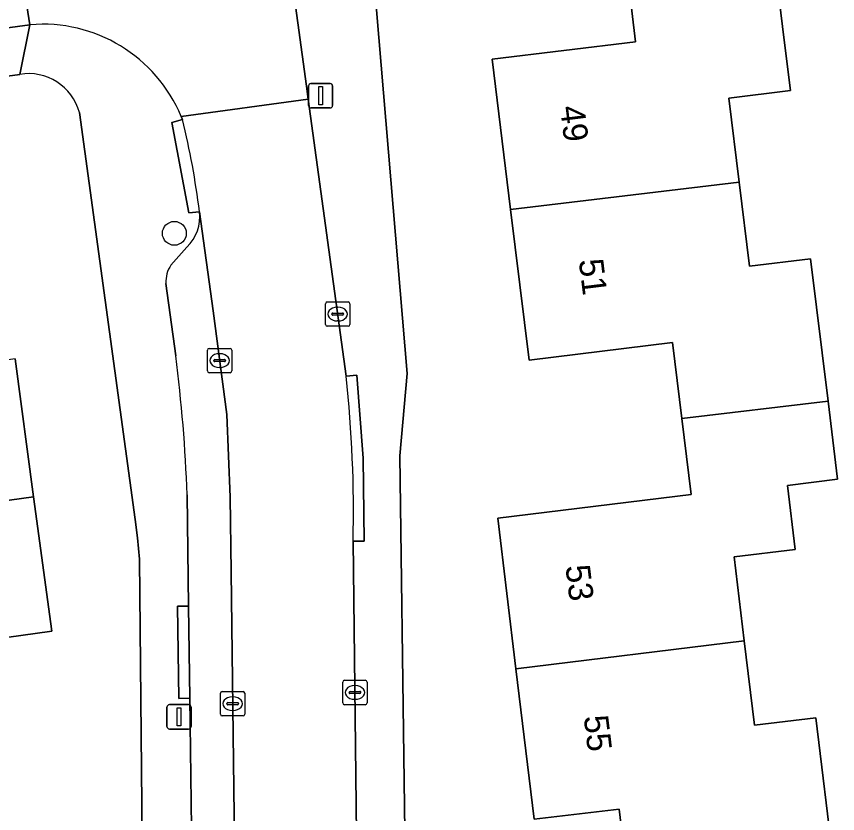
# Model space of a CAD drawing. Extents: x 163426 to 164192, y 380329 to 381641.
# Drawn here: x 163603.52 to 163637.18, y 380953.62 to 380986.28 of the extents above; entities that cross this region are included whole.
import ezdxf

# ---------------------------------------------------------------- set-up
doc = ezdxf.new("R2010")
doc.units = 0
for name, color, linetype in [('IMGEO_Boom', 7, 'Continuous'), ('IMGEO_Erf', 7, 'Continuous'), ('IMGEO_Kolk', 7, 'Continuous'), ('IMGEO_Lichtmast', 7, 'Continuous'), ('IMGEO_Pand', 7, 'Continuous'), ('IMGEO_Pand_nummerreeks', 7, 'Continuous'), ('IMGEO_Parkeervlak_open', 7, 'Continuous'), ('IMGEO_Rijbaan_lokaal_open', 7, 'Continuous'), ('IMGEO_Voetpad_open', 7, 'Continuous')]:
    doc.layers.add(name, color=color, linetype=linetype)

msp = doc.modelspace()

# ---------------------------------------------------------------- linework, layer by layer
at = {"layer": 'IMGEO_Boom'}
msp.add_circle((163609.992, 380977.393), 0.489, dxfattribs=at)
at = {"layer": 'IMGEO_Erf'}
for points in [[(163617.891, 380991.091), (163619.538, 380971.648), (163619.238, 380968.276), (163619.763, 380928.298)], [(163628.589, 380950.731), (163628.222, 380953.805), (163624.741, 380953.39), (163623.993, 380959.552), (163623.245, 380965.718), (163631.178, 380966.696), (163630.794, 380969.807), (163630.41, 380972.923), (163624.53, 380972.198), (163623.775, 380978.366), (163623.021, 380984.53), (163628.892, 380985.235), (163628.289, 380990.329)], [(163634.371, 380990.377), (163634.977, 380985.414), (163635.242, 380983.242), (163632.722, 380982.935), (163633.142, 380979.492), (163633.563, 380976.048), (163636.073, 380976.355), (163636.785, 380970.521), (163637.177, 380967.315), (163635.123, 380967.064), (163635.443, 380964.444), (163632.932, 380964.138), (163633.352, 380960.694), (163633.774, 380957.241), (163636.285, 380957.548), (163637.012, 380951.59)], [(163603.654, 380983.906), (163596.929, 380982.994)], [(163608.56, 380964.048), (163608.482, 380964.92), (163608.391, 380965.666), (163606.099, 380982.34)], [(163603.462, 380972.248), (163604.225, 380966.6), (163604.97, 380961.09), (163599.97, 380960.4)], [(163609.036, 380928.48), (163608.809, 380938.199), (163608.56, 380964.048)]]:
    msp.add_lwpolyline(points, dxfattribs=at)
msp.add_arc((163604.011, 380981.772), 2.164, 15.2262, 99.4954, dxfattribs=at)
at = {"layer": 'IMGEO_Kolk'}
for p, q in [((163616.261, 380974.584), (163617.113, 380974.584)), ((163616.186, 380973.658), (163616.186, 380974.51)), ((163616.674, 380974.364), (163616.699, 380974.364)), ((163617.187, 380974.51), (163617.187, 380973.658)), ((163616.445, 380974.078), (163616.445, 380974.09)), ((163616.883, 380974.041), (163616.485, 380974.041)), ((163616.488, 380974.127), (163616.886, 380974.127)), ((163616.929, 380974.09), (163616.929, 380974.078)), ((163617.113, 380973.584), (163616.261, 380973.584)), ((163616.697, 380973.804), (163616.672, 380973.804)), ((163611.347, 380971.754), (163611.347, 380972.606)), ((163611.422, 380972.68), (163612.274, 380972.68)), ((163612.348, 380972.606), (163612.348, 380971.754)), ((163611.649, 380972.223), (163612.047, 380972.223)), ((163611.835, 380972.46), (163611.86, 380972.46)), ((163611.606, 380972.174), (163611.606, 380972.186)), ((163612.044, 380972.137), (163611.646, 380972.137)), ((163611.858, 380971.9), (163611.833, 380971.9)), ((163612.09, 380972.186), (163612.09, 380972.174)), ((163612.274, 380971.68), (163611.422, 380971.68)), ((163616.892, 380958.156), (163616.892, 380959.008)), ((163616.967, 380959.082), (163617.819, 380959.082)), ((163617.38, 380958.862), (163617.405, 380958.862)), ((163617.893, 380959.008), (163617.893, 380958.156)), ((163611.881, 380957.697), (163611.881, 380958.549)), ((163611.956, 380958.623), (163612.808, 380958.623)), ((163612.882, 380958.549), (163612.882, 380957.697)), ((163617.151, 380958.576), (163617.151, 380958.588)), ((163617.589, 380958.539), (163617.191, 380958.539)), ((163617.194, 380958.625), (163617.592, 380958.625)), ((163617.635, 380958.588), (163617.635, 380958.576)), ((163612.14, 380958.117), (163612.14, 380958.129)), ((163612.578, 380958.08), (163612.18, 380958.08)), ((163612.183, 380958.166), (163612.581, 380958.166)), ((163612.369, 380958.403), (163612.394, 380958.403)), ((163612.624, 380958.129), (163612.624, 380958.117)), ((163617.819, 380958.082), (163616.967, 380958.082)), ((163617.403, 380958.302), (163617.378, 380958.302)), ((163612.392, 380957.843), (163612.367, 380957.843)), ((163612.808, 380957.623), (163611.956, 380957.623))]:
    msp.add_line(p, q, dxfattribs=at)
for points in [[(163616.261, 380974.584), (163617.113, 380974.584)], [(163616.186, 380973.658), (163616.186, 380974.51)], [(163617.187, 380974.51), (163617.187, 380973.658)], [(163617.113, 380973.584), (163616.261, 380973.584)], [(163611.347, 380971.754), (163611.347, 380972.606)], [(163611.422, 380972.68), (163612.274, 380972.68)], [(163612.348, 380972.606), (163612.348, 380971.754)], [(163612.274, 380971.68), (163611.422, 380971.68)], [(163616.892, 380958.156), (163616.892, 380959.008)], [(163616.967, 380959.082), (163617.819, 380959.082)], [(163617.893, 380959.008), (163617.893, 380958.156)], [(163611.881, 380957.697), (163611.881, 380958.549)], [(163611.956, 380958.623), (163612.808, 380958.623)], [(163612.882, 380958.549), (163612.882, 380957.697)], [(163617.819, 380958.082), (163616.967, 380958.082)], [(163612.808, 380957.623), (163611.956, 380957.623)]]:
    msp.add_lwpolyline(points, dxfattribs=at)
for centre, radius, start, end in [((163616.263, 380974.508), 0.0765, 91.552, 178.448), ((163616.263, 380974.508), 0.0765, 91.552, 178.448), ((163617.111, 380974.508), 0.0765, 1.552, 88.448), ((163617.111, 380974.508), 0.0765, 1.552, 88.448), ((163616.485, 380974.087), 0.0403, 85.8775, 175.7526), ((163616.482, 380974.077), 0.0366, 178.938, 274.7102), ((163616.886, 380974.084), 0.043, 264.8664, 352.4533), ((163616.89, 380974.089), 0.0386, 1.7309, 96.639), ((163616.263, 380973.66), 0.0765, 181.552, 268.448), ((163616.263, 380973.66), 0.0765, 181.552, 268.448), ((163617.111, 380973.66), 0.0765, 271.552, 358.448), ((163617.111, 380973.66), 0.0765, 271.552, 358.448), ((163611.424, 380972.604), 0.0765, 91.552, 178.448), ((163611.424, 380972.604), 0.0765, 91.552, 178.448), ((163612.272, 380972.604), 0.0765, 1.552, 88.448), ((163612.272, 380972.604), 0.0765, 1.552, 88.448), ((163611.646, 380972.183), 0.0403, 85.8775, 175.7526), ((163612.051, 380972.185), 0.0386, 1.7309, 96.639), ((163611.643, 380972.173), 0.0366, 178.938, 274.7102), ((163612.047, 380972.18), 0.043, 264.8664, 352.4533), ((163611.424, 380971.756), 0.0765, 181.552, 268.448), ((163611.424, 380971.756), 0.0765, 181.552, 268.448), ((163612.272, 380971.756), 0.0765, 271.552, 358.448), ((163612.272, 380971.756), 0.0765, 271.552, 358.448), ((163616.969, 380959.006), 0.0765, 91.552, 178.448), ((163616.969, 380959.006), 0.0765, 91.552, 178.448), ((163617.817, 380959.006), 0.0765, 1.552, 88.448), ((163617.817, 380959.006), 0.0765, 1.552, 88.448), ((163611.958, 380958.547), 0.0765, 91.552, 178.448), ((163611.958, 380958.547), 0.0765, 91.552, 178.448), ((163612.806, 380958.547), 0.0765, 1.552, 88.448), ((163612.806, 380958.547), 0.0765, 1.552, 88.448), ((163617.191, 380958.585), 0.0403, 85.8775, 175.7526), ((163617.188, 380958.575), 0.0366, 178.938, 274.7102), ((163617.592, 380958.582), 0.043, 264.8664, 352.4533), ((163617.596, 380958.587), 0.0386, 1.7309, 96.639), ((163612.18, 380958.126), 0.0403, 85.8775, 175.7526), ((163612.177, 380958.116), 0.0366, 178.938, 274.7102), ((163612.581, 380958.123), 0.043, 264.8664, 352.4533), ((163612.585, 380958.128), 0.0386, 1.7309, 96.639), ((163616.969, 380958.158), 0.0765, 181.552, 268.448), ((163616.969, 380958.158), 0.0765, 181.552, 268.448), ((163617.817, 380958.158), 0.0765, 271.552, 358.448), ((163617.817, 380958.158), 0.0765, 271.552, 358.448), ((163611.958, 380957.699), 0.0765, 181.552, 268.448), ((163611.958, 380957.699), 0.0765, 181.552, 268.448), ((163612.806, 380957.699), 0.0765, 271.552, 358.448), ((163612.806, 380957.699), 0.0765, 271.552, 358.448)]:
    msp.add_arc(centre, radius, start, end, dxfattribs=at)
for centre, major_axis, ratio, start_param, end_param in [((163616.673, 380974.084), (-0.387, 0.002), 0.722429, 4.712389, 7.853982), ((163616.698, 380974.084), (-0.39, 0.002), 0.717154, 1.570796, 4.712389), ((163611.834, 380972.18), (-0.387, 0.002), 0.722429, 4.712389, 7.853982), ((163611.859, 380972.18), (-0.39, 0.002), 0.717154, 1.570796, 4.712389), ((163617.379, 380958.582), (-0.387, 0.002), 0.722429, 4.712389, 7.853982), ((163617.404, 380958.582), (-0.39, 0.002), 0.717154, 1.570796, 4.712389), ((163612.368, 380958.123), (-0.387, 0.002), 0.722429, 4.712389, 7.853982), ((163612.393, 380958.123), (-0.39, 0.002), 0.717154, 1.570796, 4.712389)]:
    msp.add_ellipse(centre, major_axis=major_axis, ratio=ratio, start_param=start_param, end_param=end_param, dxfattribs=at)
at = {"layer": 'IMGEO_Lichtmast'}
for p, q in [((163615.49, 380982.629), (163615.49, 380983.429)), ((163615.49, 380983.429), (163615.49, 380982.629)), ((163615.59, 380983.529), (163616.38, 380983.529)), ((163616.38, 380983.529), (163615.59, 380983.529)), ((163616.48, 380983.429), (163616.48, 380982.629)), ((163616.48, 380982.629), (163616.48, 380983.429)), ((163616.38, 380982.529), (163615.59, 380982.529)), ((163615.59, 380982.529), (163616.38, 380982.529)), ((163609.789, 380958.085), (163610.579, 380958.085)), ((163610.579, 380958.085), (163609.789, 380958.085)), ((163609.689, 380957.185), (163609.689, 380957.985)), ((163609.689, 380957.985), (163609.689, 380957.185)), ((163610.679, 380957.985), (163610.679, 380957.185)), ((163610.679, 380957.185), (163610.679, 380957.985)), ((163610.579, 380957.085), (163609.789, 380957.085)), ((163609.789, 380957.085), (163610.579, 380957.085))]:
    msp.add_line(p, q, dxfattribs=at)
for points in [[(163615.91, 380983.404), (163616.06, 380983.404), (163616.06, 380982.654), (163615.91, 380982.654), (163615.91, 380983.404)], [(163610.109, 380957.96), (163610.259, 380957.96), (163610.259, 380957.21), (163610.109, 380957.21), (163610.109, 380957.96)]]:
    msp.add_lwpolyline(points, dxfattribs=at)
for centre, start, end in [((163615.59, 380983.429), 90, 180), ((163615.59, 380983.429), 90, 180), ((163616.38, 380983.429), 0, 90), ((163616.38, 380983.429), 360, 90), ((163615.59, 380982.629), 180, 270), ((163615.59, 380982.629), 180, 270), ((163616.38, 380982.629), 270, 0), ((163616.38, 380982.629), 270, 0), ((163609.789, 380957.985), 90, 180), ((163609.789, 380957.985), 90, 180), ((163610.579, 380957.985), 0, 90), ((163610.579, 380957.985), 360, 90), ((163609.789, 380957.185), 180, 270), ((163609.789, 380957.185), 180, 270), ((163610.579, 380957.185), 270, 0), ((163610.579, 380957.185), 270, 0)]:
    msp.add_arc(centre, 0.1, start, end, dxfattribs=at)
at = {"layer": 'IMGEO_Pand'}
for points in [[(163634.977, 380985.414), (163634.371, 380990.377), (163633.385, 380990.42), (163627.777, 380990.665), (163627.769, 380990.347), (163628.289, 380990.329), (163628.892, 380985.235), (163623.021, 380984.53), (163623.775, 380978.366), (163633.142, 380979.492), (163632.722, 380982.935), (163635.242, 380983.242)], [(163633.142, 380979.492), (163623.775, 380978.366), (163624.53, 380972.198), (163630.41, 380972.923), (163630.794, 380969.807), (163636.785, 380970.521), (163636.073, 380976.355), (163633.563, 380976.048)], [(163595.332, 380965.365), (163604.225, 380966.6), (163603.462, 380972.248), (163594.567, 380971.024)], [(163623.993, 380959.552), (163633.352, 380960.694), (163632.932, 380964.138), (163635.443, 380964.444), (163635.123, 380967.064), (163637.177, 380967.315), (163636.785, 380970.521), (163630.794, 380969.807), (163631.178, 380966.696), (163623.245, 380965.718)], [(163595.332, 380965.365), (163596.061, 380959.975), (163593.732, 380959.66), (163594.148, 380956.588), (163595.416, 380956.76), (163600.37, 380957.43), (163599.97, 380960.4), (163604.97, 380961.09), (163604.225, 380966.6)], [(163636.285, 380957.548), (163633.774, 380957.241), (163633.352, 380960.694), (163623.993, 380959.552), (163624.741, 380953.39), (163628.222, 380953.805), (163628.589, 380950.731), (163628.608, 380950.572), (163629.044, 380950.625), (163637.012, 380951.59)]]:
    msp.add_lwpolyline(points, close=True, dxfattribs=at)
at = {"layer": 'IMGEO_Parkeervlak_open'}
for points in [[(163612.784, 380925.796), (163612.316, 380963.521), (163612.276, 380966.585), (163612.142, 380969.964), (163611.579, 380974.223), (163611.021, 380978.28)], [(163610.51, 380976.833), (163609.853, 380976.094)], [(163609.644, 380975.342), (163610.051, 380972.374)], [(163610.518, 380966.674), (163610.576, 380962.115), (163610.624, 380958.353), (163611.003, 380928.527)]]:
    msp.add_lwpolyline(points, dxfattribs=at)
for centre, radius, start, end in [((163609.325, 380978.065), 1.71, 313.8819, 7.2174), ((163610.868, 380975.407), 1.225, 145.8966, 183.0395), ((163545.326, 380964.202), 65.239, 2.1716, 7.19595)]:
    msp.add_arc(centre, radius, start, end, dxfattribs=at)
at = {"layer": 'IMGEO_Rijbaan_lokaal_open'}
for points in [[(163610.277, 380982.177), (163615.484, 380982.891), (163615.411, 380983.425), (163613.138, 381000)], [(163535.429, 380976.678), (163539.492, 380977.239), (163540.851, 380977.426), (163542.875, 380977.704), (163543.642, 380977.799), (163547.389, 380978.306), (163558.005, 380979.727), (163564.743, 380980.629), (163574.92, 380981.991), (163581.655, 380982.903), (163604.072, 380985.939), (163603.292, 380990.858), (163541.544, 380982.579), (163541.403, 380982.56), (163540.361, 380982.447)], [(163603.292, 380990.858), (163604.072, 380985.939)], [(163617.035, 380971.535), (163615.484, 380982.891), (163610.277, 380982.177), (163610.326, 380982.053)], [(163611.021, 380978.28), (163611.579, 380974.223), (163612.142, 380969.964), (163612.276, 380966.585), (163612.316, 380963.521), (163612.784, 380925.796), (163612.755, 380923.859)], [(163617.464, 380952.783), (163617.315, 380964.783)]]:
    msp.add_lwpolyline(points, dxfattribs=at)
for centre, radius, start, end in [((163604.598, 380979.808), 6.153, 22.6416, 94.9028), ((163579.216, 380974.372), 32.044, 7.0051, 13.869), ((163565.899, 380966.033), 51.432, 358.6078, 6.1415)]:
    msp.add_arc(centre, radius, start, end, dxfattribs=at)
at = {"layer": 'IMGEO_Voetpad_open'}
for points in [[(163619.238, 380968.276), (163619.538, 380971.648), (163617.891, 380991.091), (163617.735, 380991.057), (163617.259, 380994.533), (163617.031, 380996.193), (163616.544, 380999.748), (163603.525, 381095.083), (163603.447, 381095.786), (163602.972, 381100.077)], [(163612.89, 381001.887), (163613.016, 381000.89), (163613.059, 381000.578), (163613.138, 381000), (163615.411, 380983.425), (163615.484, 380982.891), (163617.035, 380971.535), (163617.466, 380971.576), (163617.725, 380968.185), (163617.767, 380964.784), (163617.315, 380964.783), (163617.464, 380952.783), (163617.907, 380952.825), (163617.998, 380946.038), (163617.548, 380946.038), (163617.688, 380934.784), (163618.138, 380934.805), (163618.208, 380930.291), (163617.744, 380930.287), (163617.801, 380925.684), (163621.755, 380926.366)], [(163604.072, 380985.939), (163603.654, 380983.906)], [(163606.099, 380982.34), (163608.391, 380965.666), (163608.482, 380964.92), (163608.56, 380964.048), (163608.809, 380938.199), (163609.036, 380928.48)], [(163611.021, 380978.28), (163610.585, 380978.228), (163609.888, 380981.931), (163610.326, 380982.053), (163610.277, 380982.177)], [(163610.326, 380982.053), (163609.888, 380981.931), (163610.585, 380978.228), (163611.021, 380978.28)], [(163609.853, 380976.094), (163610.51, 380976.833)], [(163610.051, 380972.374), (163609.644, 380975.342)], [(163617.315, 380964.783), (163617.767, 380964.784), (163617.725, 380968.185), (163617.466, 380971.576), (163617.035, 380971.535)], [(163619.763, 380928.298), (163619.238, 380968.276)], [(163611.003, 380928.527), (163610.624, 380958.353), (163610.177, 380958.333), (163610.118, 380962.123), (163610.576, 380962.115), (163610.518, 380966.674)]]:
    msp.add_lwpolyline(points, dxfattribs=at)
for points in [[(163590.68, 380982.146), (163596.929, 380982.994), (163603.654, 380983.906), (163604.072, 380985.939), (163581.655, 380982.903), (163574.92, 380981.991), (163564.743, 380980.629), (163558.005, 380979.727), (163547.389, 380978.306), (163543.642, 380977.799), (163542.875, 380977.704), (163540.851, 380977.426), (163541.047, 380975.415), (163581.54, 380980.906)], [(163610.624, 380958.353), (163610.576, 380962.115), (163610.118, 380962.123), (163610.177, 380958.333)]]:
    msp.add_lwpolyline(points, close=True, dxfattribs=at)
for centre, radius, start, end in [((163604.598, 380979.808), 6.153, 22.6416, 94.9028), ((163604.011, 380981.772), 2.164, 15.2262, 99.4954), ((163579.216, 380974.372), 32.044, 7.0051, 13.869), ((163609.325, 380978.065), 1.71, 313.8819, 7.2174), ((163610.868, 380975.407), 1.225, 145.8966, 183.0395), ((163545.326, 380964.202), 65.239, 2.1716, 7.19595), ((163565.899, 380966.033), 51.432, 358.6078, 6.1415)]:
    msp.add_arc(centre, radius, start, end, dxfattribs=at)

# ---------------------------------------------------------------- texts
at = {"layer": 'IMGEO_Pand_nummerreeks'}
for s, rotation, p in [('49', 276.9784, (163625.799, 380982.573)), ('51', 276.9763, (163626.567, 380976.294)), ('53', 276.919, (163626.021, 380963.759)), ('55', 276.9211, (163626.769, 380957.595))]:
    msp.add_text(s, height=1, rotation=rotation, dxfattribs=at).set_placement(p)

doc.saveas('drawing.dxf')
